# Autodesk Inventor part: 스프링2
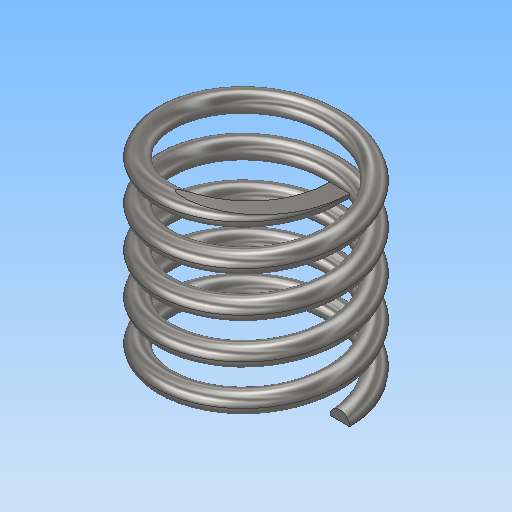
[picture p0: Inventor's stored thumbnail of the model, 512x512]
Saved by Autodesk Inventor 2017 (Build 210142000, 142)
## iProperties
Part Number: 스프링2
Material: 스테인레스 스틸
Document SubType Name: Modeling
Designer: MRC
Density: 8 g/cm^3
Appearance: 반연마
Mass: 6.57245 g
Surface Area: 16.7217 cm^2
Volume: 0.821556 cm^3
Author: MRC
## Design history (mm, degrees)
sketch "스케치1"
  geometry: L1 (0, 0)-(0, 20.5); L2 (0, 0)-(8.5, 0); L3 (0, 20.5)-(8.5, 20.5); C1 r 1 at (8.5, 0)
  constraints: 6 end point, 2 horizontal, 1 centre point, 1 coincident, 1 parallel, 1 vertical
  dimensions: "d0" = 20.5 distance of L1.start L1.end (derived); "d1" = 2 diameter of C1; "d2" = 17 diameter of L2.end L1
feature "코일1" sketch "스케치1" pitch "d3" = 10; turns "d5" = 5; dims "d4" = 20.5 (= d0), "d6" = 0, angle "d7" = 90 deg, angle "d8" = 90 deg, "d9" = 0, "d10" = 0
sketch "스케치2"
  geometry: L1 (20.5, 10)-(0, 10); L2 (0, 10)-(0, -10); L3 (0, -10)-(20.5, -10); L4 (20.5, -10)-(20.5, 10); 2 further points
  constraints: 8 end point, 2 parallel, 1 coincident, 1 horizontal, 1 midpoint, 1 perpendicular
  dimensions: "d11" = 20.5 distance of L2.end L3.end (= d0); "d12" = 20 distance of L3.end L1.start
extrude "돌출1" sketch "스케치2" stored distance "d13" = 0; taper "d14" = 0 deg
node "솔리드1"
